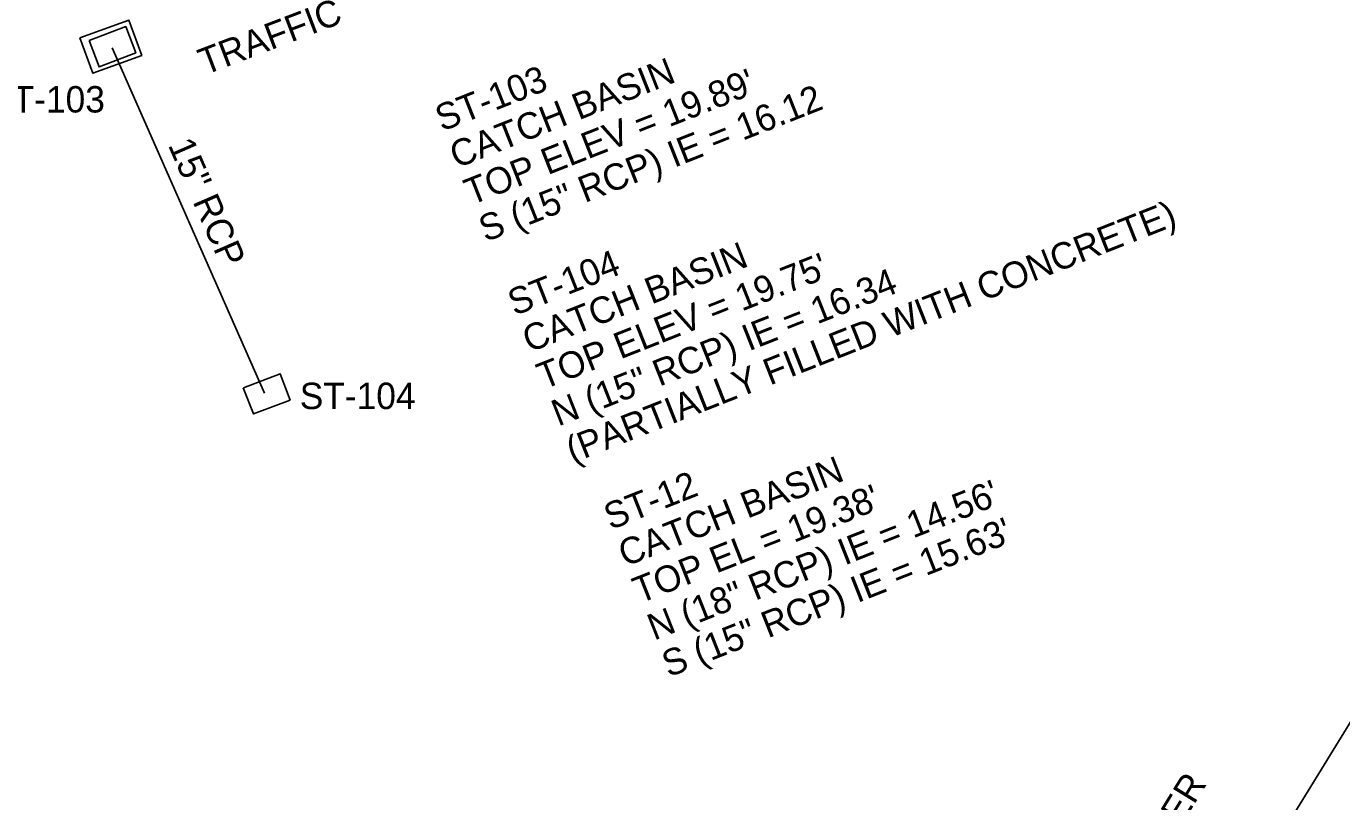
# Model space of a CAD drawing. Extents: x 509744 to 512285, y 1314862 to 1316822.
# Drawn here: x 510339.7 to 510479.2, y 1315227.8 to 1315310 of the extents above; entities that cross this region are included whole.
import ezdxf

# ---------------------------------------------------------------- set-up
doc = ezdxf.new("R2010")
doc.units = 0
for name, color, linetype in [('CatchBasin_ep', 7, 'Continuous'), ('ConcSlabs_ep', 7, 'Continuous'), ('LARWLine_ep', 7, 'Continuous'), ('NonPlottingEle_dp', 7, 'Continuous'), ('PipeCulvert_ep', 7, 'Continuous'), ('TextNotes', 7, 'Continuous'), ('TextTopoLabel_ep', 7, 'Continuous')]:
    doc.layers.add(name, color=color, linetype=linetype)

msp = doc.modelspace()

# ---------------------------------------------------------------- linework, layer by layer
at = {"layer": 'CatchBasin_ep'}
msp.add_lwpolyline([(510346.39, 1315308.44), (510350.29, 1315309.93), (510351.35, 1315307.15), (510347.45, 1315305.66)], close=True, dxfattribs=at)
msp.add_lwpolyline([(510362.76, 1315271.63), (510366.66, 1315273.12), (510367.72, 1315270.34), (510363.82, 1315268.86), (510362.73, 1315271.62)], dxfattribs=at)
at = {"layer": 'ConcSlabs_ep'}
msp.add_lwpolyline([(510345.42, 1315308.72), (510350.62, 1315310.61), (510351.98, 1315306.87), (510346.78, 1315304.98)], close=True, dxfattribs=at)
at = {"layer": 'LARWLine_ep'}
msp.add_line((510414.96, 1315130.24), (510554.46, 1315356.98), dxfattribs=at)
at = {"layer": 'PipeCulvert_ep'}
msp.add_line((510348.84, 1315307.67), (510365, 1315271.08), dxfattribs=at)

# ---------------------------------------------------------------- texts
at = {"layer": 'NonPlottingEle_dp'}
for s, rotation, p in [('ST-103', 21.5246, (510383.82, 1315298.78)), ('CATCH BASIN', 21.5246, (510385.36, 1315294.87)), ("TOP ELEV = 19.89'", 21.5246, (510386.9, 1315290.96)), ('S (15" RCP) IE = 16.12', 21.5246, (510388.44, 1315287.06)), ('15" RCP', 293.6323, (510354.73, 1315297.38)), ('(PARTIALLY FILLED WITH CONCRETE)', 21.5246, (510397.69, 1315263.62)), ('ST-104', 21.5246, (510391.52, 1315279.24)), ('CATCH BASIN', 21.5246, (510393.07, 1315275.34)), ("TOP ELEV = 19.75'", 21.5246, (510394.61, 1315271.43)), ('N (15" RCP) IE = 16.34', 21.5246, (510396.15, 1315267.52)), ('CATCH BASIN', 21.5246, (510403.24, 1315252.63)), ('ST-12', 21.5246, (510401.7, 1315256.54)), ("TOP EL = 19.38'", 21.5246, (510404.78, 1315248.73)), ('N (18" RCP) IE = 14.56\'', 21.5246, (510406.32, 1315244.82)), ('S (15" RCP) IE = 15.63\'', 21.5246, (510407.86, 1315240.91))]:
    msp.add_text(s, height=2.8, rotation=rotation, dxfattribs=at).set_placement(p)
for s, p in [('ST-103', (510335.79, 1315300.82)), ('ST-104', (510368.74, 1315269.38))]:
    msp.add_text(s, height=2.8, dxfattribs=at).set_placement(p)
at = {"layer": 'TextNotes'}
msp.add_text('EXISTING L.A. R/W LINE PER', height=2.8, rotation=58.3964, dxfattribs=at).set_placement((510437.96, 1315185.73))
at = {"layer": 'TextTopoLabel_ep'}
msp.add_text('TRAFFIC', height=2.8, rotation=20.866, dxfattribs=at).set_placement((510358.67, 1315304.76))

doc.saveas('drawing.dxf')
